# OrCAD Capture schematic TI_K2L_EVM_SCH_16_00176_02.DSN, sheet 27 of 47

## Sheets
27 PAGE16 : K2L_SOC-FPGA-AMC-2: size C; title: FPGA, FPGA 2pin conn, SPI Flash, LEDs
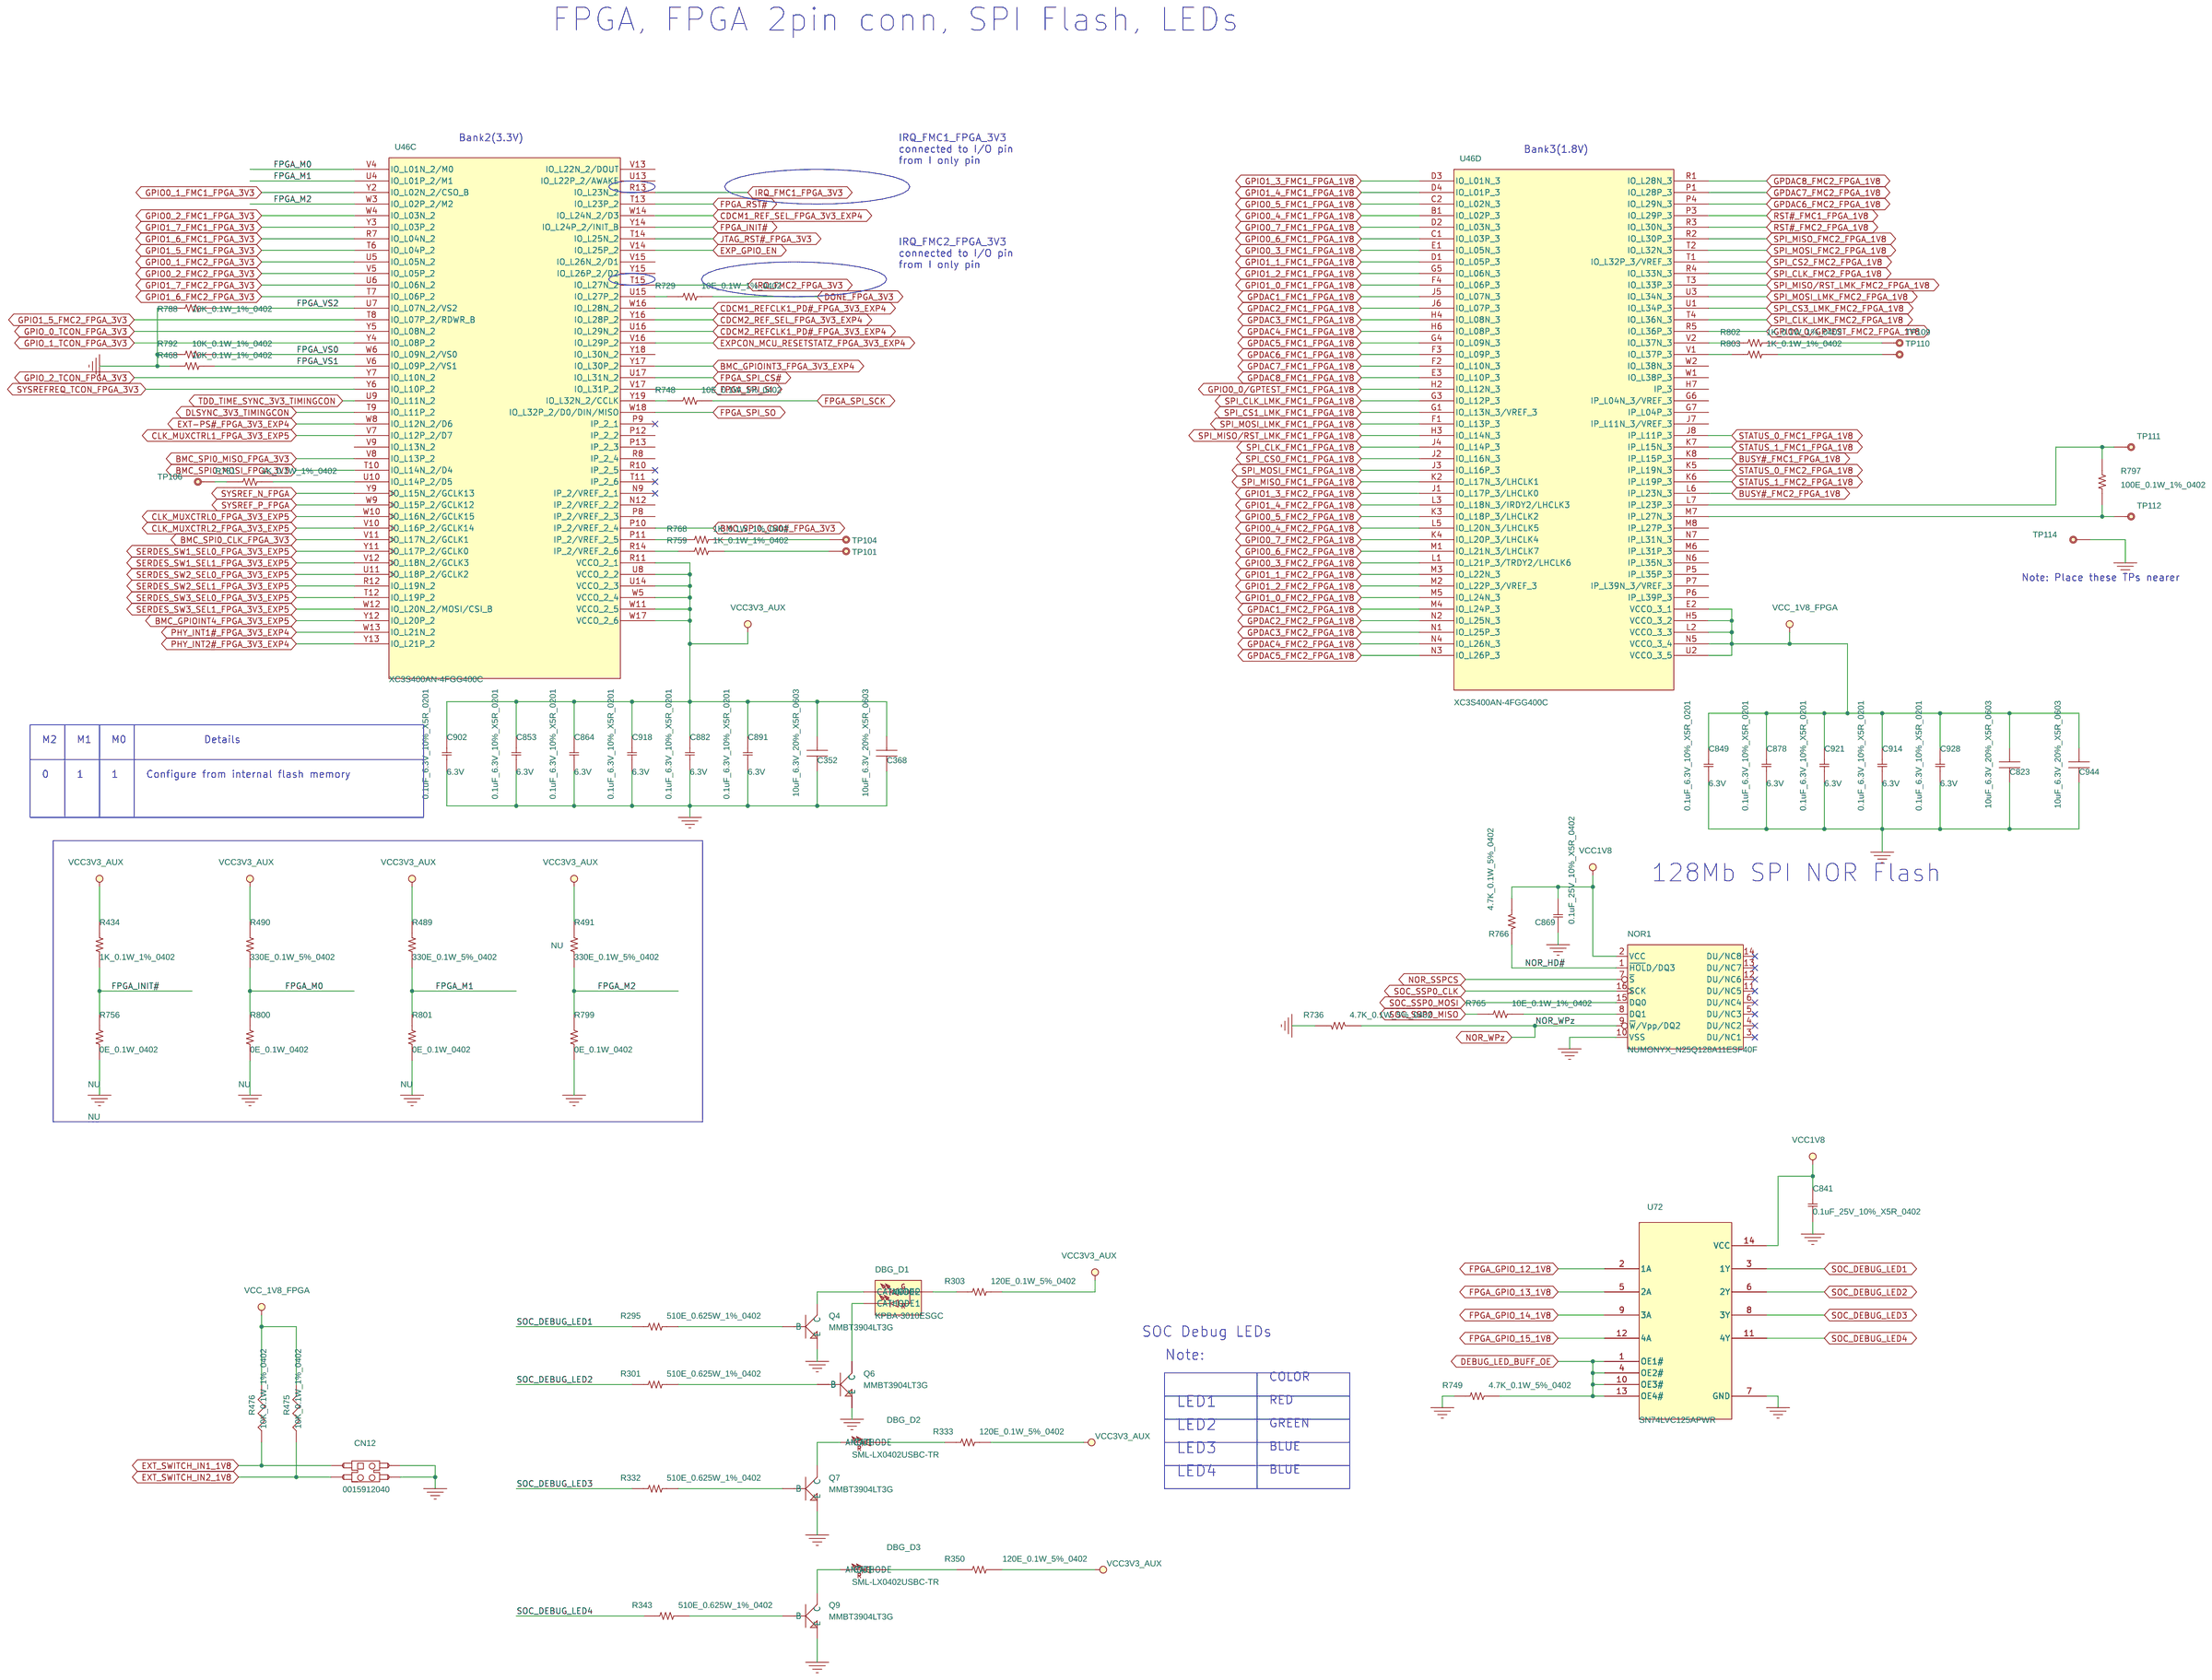
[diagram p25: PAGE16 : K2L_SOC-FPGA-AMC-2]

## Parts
sheet PAGE16 : K2L_SOC-FPGA-AMC-2
C352  10uF_6.3V_20%_X5R_0603  [C0603]
C368  10uF_6.3V_20%_X5R_0603  [C0603]
C823  10uF_6.3V_20%_X5R_0603  [C0603]
C841  0.1uF_25V_10%_X5R_0402  [C0402]
C849  0.1uF_6.3V_10%_X5R_0201  [CC0201_IPC7351_EINF]
C853  0.1uF_6.3V_10%_X5R_0201  [CC0201_IPC7351_EINF]
C864  0.1uF_6.3V_10%_X5R_0201  [CC0201_IPC7351_EINF]
C869  0.1uF_25V_10%_X5R_0402  [C0402]
C878  0.1uF_6.3V_10%_X5R_0201  [CC0201_IPC7351_EINF]
C882  0.1uF_6.3V_10%_X5R_0201  [CC0201_IPC7351_EINF]
C891  0.1uF_6.3V_10%_X5R_0201  [CC0201_IPC7351_EINF]
C902  0.1uF_6.3V_10%_X5R_0201  [CC0201_IPC7351_EINF]
C914  0.1uF_6.3V_10%_X5R_0201  [CC0201_IPC7351_EINF]
C918  0.1uF_6.3V_10%_X5R_0201  [CC0201_IPC7351_EINF]
C921  0.1uF_6.3V_10%_X5R_0201  [CC0201_IPC7351_EINF]
C928  0.1uF_6.3V_10%_X5R_0201  [CC0201_IPC7351_EINF]
C944  10uF_6.3V_20%_X5R_0603  [C0603]
CN12  15912040  [MOLEX_0015912040]
DBG_D1  KPBA-3010ESGC  [LED_KPBA-3010ESGC-F01]
DBG_D2  SML-LX0402USBC-TR  [LED_SML-LX0402]
DBG_D3  SML-LX0402USBC-TR  [LED_SML-LX0402]
NOR1  NUMONYX_N25Q128A11ESF40F  [SOIC_16P_50_406X406]
Q4  MMBT3904LT3G  [SOT-23]
Q6  MMBT3904LT3G  [SOT-23]
Q7  MMBT3904LT3G  [SOT-23]
Q9  MMBT3904LT3G  [SOT-23]
R295  510E_0.625W_1%_0402  [R0402]
R301  510E_0.625W_1%_0402  [R0402]
R303  120E_0.1W_5%_0402  [R0402]
R332  510E_0.625W_1%_0402  [R0402]
R333  120E_0.1W_5%_0402  [R0402]
R343  510E_0.625W_1%_0402  [R0402]
R350  120E_0.1W_5%_0402  [R0402]
R434  1K_0.1W_1%_0402  [R0402]
R468  10K_0.1W_1%_0402  [R0402]
R475  10K_0.1W_1%_0402  [R0402]
R476  10K_0.1W_1%_0402  [R0402]
R489  330E_0.1W_5%_0402  [R0402]
R490  330E_0.1W_5%_0402  [R0402]
R491  330E_0.1W_5%_0402  [R0402]
R729  10E_0.1W_1%_0402  [R0402]
R736  4.7K_0.1W_5%_0402  [R0402]
R748  10E_0.1W_1%_0402  [R0402]
R749  4.7K_0.1W_5%_0402  [R0402]
R756  0E_0.1W_0402  [R0402]
R759  1K_0.1W_1%_0402  [R0402]
R765  10E_0.1W_1%_0402  [R0402]
R766  4.7K_0.1W_5%_0402  [R0402]
R768  1K_0.1W_1%_0402  [R0402]
R781  1K_0.1W_1%_0402  [R0402]
R788  10K_0.1W_1%_0402  [R0402]
R792  10K_0.1W_1%_0402  [R0402]
R797  100E_0.1W_1%_0402  [R0402]
R799  0E_0.1W_0402  [R0402]
R800  0E_0.1W_0402  [R0402]
R801  0E_0.1W_0402  [R0402]
R802  1K_0.1W_1%_0402  [R0402]
R803  1K_0.1W_1%_0402  [R0402]
TP101  TP  [TP-S40]
TP104  TP  [TP-S40]
TP106  TP  [TP-S40]
TP109  TP  [TP-S40]
TP110  TP  [TP-S40]
TP111  TP  [TP-S40]
TP112  TP  [TP-S40]
TP114  TP  [TP-S40]
U72  SN74LVC125APWR  [SSOP65P640_14]
sheet PAGE17 : K2L_SOC-FPGA-AMC-3
U46  XC3S400AN-4FGG400C  [BGA400C100P20X20_2100X2100X243]  (sections A,B,C,D,E,F)

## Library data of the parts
C352 C368 C823 C944 = CAP: CAP CER 10UF 6.3V 20% X5R 0603; Distributor_name: DIGIKEY; Distributor_part_number: 587-3383-1-ND; EIC Part#: 03_00605_01; Manufacture: Taiyo Yuden; Manufacture Part Number: JMK107ABJ106MAHT; Manufacture(English): Taiyo Yuden; Manufacture_Part_Number: JMK107ABJ106MAHT; Manufacturer: Taiyo Yuden; Manufacturer_Part_No: JMK107ABJ106MAHT; Mfg: Taiyo Yuden; Mfg Part#: JMK107ABJ106MAHT; Mfr_name: Taiyo Yuden; Mfr_part_number: JMK107ABJ106MAHT; Price @ 1: 0.44000; Price @ 10K: 0.06105; Price @ 1K: 0.12650; Vendor: DIGIKEY; Vendor_Part_No: 587-3383-1-ND; eI Part#: 03_00605_01
C841 = 11_C_12: CAP CER 0.1UF 25V 10% X5R 0402; Distributor_name: DIGIKEY; Distributor_part_number: 445-4964-1-ND; EIC Part#: 03_00470_02; Manufacture: TDK Corporation; Manufacture Part Number: C1005X5R1E104K050BC; Manufacture(English): TDK Corporation; Manufacture_Part_Number: GRM155R61E104KA87D; Manufacturer: TDK Corporation; Manufacturer_Part_No: C1005X5R1E104K050BC; Mfg: Murata Electronics North America; Mfg Part#: 03_00470_02; Mfr_name: TDK Corporation; Mfr_part_number: C1005X5R1E104K050BC; Price @ 1: 0.10000; Price @ 1K: 0.00960; Vendor: DIGIKEY; Vendor Part#: 445-4964-1-ND; Vendor_Part_No: 445-4964-1-ND; eI Part#: 03_00470_02
C849 C853 C864 C878 C882 C891 C902 C914 C918 C921 C928 = 11_C_12: CAP CER 0.1UF 6.3V 10% X5R 0201; Alt Mfg: Taiyo Yuden; Alt Mfg Part#: TMK105BJ104KV-F; Characteristic: <Characteristic>; Distributor_name: DIGIKEY; Distributor_part_number: 445-1796-1-ND; EIC Part#: 03_00583_01; Manufacture: TDK Corporation; Manufacture Part Number: C0603X5R0J104K030BC; Manufacture(English): TDK Corporation; Manufacture_Part_Number: C0603X5R0J104K030BC; Manufacturer: TDK Corporation; Manufacturer_Part_No: C0603X5R0J104K030BC; Mfg: TDK Corporation; Mfg Part#: 03_00583_01; Mfr_name: TDK Corporation; Mfr_part_number: C0603X5R0J104K030BC; Oper. Temp. Range: -55°C ~ 85°C; Package: 0201; Price @ 1: 0.10000; Price @ 10K: 0.00675; Price @ 1K: 0.00810; ProcessType: SMT; RoHS: Yes; Tolerance: 10%; Vendor: DIGIKEY; Vendor Part#: 445-1796-2-ND; Vendor_Part_No: 445-1796-1-ND; Voltage: 6.3V; eI Part#: 03_00583_01
C869 = 11_C_0: CAP CER 0.1UF 25V 10% X5R 0402; Distributor_name: DIGIKEY; Distributor_part_number: 445-4964-1-ND; EIC Part#: 03_00470_02; Manufacture: TDK Corporation; Manufacture Part Number: C1005X5R1E104K050BC; Manufacture(English): TDK Corporation; Manufacture_Part_Number: GRM155R61E104KA87D; Manufacturer: TDK Corporation; Manufacturer_Part_No: C1005X5R1E104K050BC; Mfg: Murata Electronics North America; Mfg Part#: 03_00470_02; Mfr_name: TDK Corporation; Mfr_part_number: C1005X5R1E104K050BC; Price @ 1: 0.10000; Price @ 1K: 0.00960; Vendor: DIGIKEY; Vendor Part#: 445-4964-1-ND; Vendor_Part_No: 445-4964-1-ND; eI Part#: 03_00470_02
CN12 = XG8T-0441_0: CONN HEADER 4POS TIN SMD; Characteristic: 0015912040; Distributor_name: DIGIKEY; Distributor_part_number: WM9514-ND; EIC Part#: TBD; Manufacture: Molex Inc; Manufacture(English): Molex Inc; Manufacture_Part_Number: 0015912040; Manufacturer: Molex Inc; Mfg: Molex Inc; Mfg Part#: TBD; Mfr_name: Molex Inc; Price @ 1: 0.42000; Price @ 10K: 0.19770; Price @ 1K: 0.21247; Vendor: DIGIKEY; Vendor_Part_No: WM9514-ND; eI Part#: TBD
DBG_D1 = 130_LED_3P_KPBA-3010ESGC_0: LED Red/Green SMD 3.0x1.0mm 3P KPBA-3010ESGC; Distributor_name: Avnet Express; Distributor_part_number: KINKPBA3010ESGC; EIC Part#: TBD; Manufacture: Kingbright Corporation; Manufacture Part Number: KPBA-3010ESGC-F01; Manufacture(English): Kingbright Corporation; Manufacture_Part_Number: KPBA-3010ESGC-F01; Manufacturer: Kingbright Corporation; Manufacturer_Part_No: KPBA-3010ESGC-F01; Mfg: Kingbright Corporation; Mfg Part#: TBD; Mfr_name: Kingbright Corporation; Mfr_part_number: KPBA-3010ESGC-F01; Price @ 1: 0.68000; Price @ 10K: 0.34000; Price @ 1K: 0.34000; Vendor: Avnet Express; Vendor_Part_No: KINKPBA3010ESGC; eI Part#: TBD
DBG_D2 DBG_D3 = 130_LED_2P_B_KPA-1606QBC-D_2: Standard LEDs - SMD Blue Water Clear 470nm 20mcd; Distributor_name: Mouser; EIC Part#: TBD; Manufacture: Lumex Inc; Manufacture(English): Lumex Inc; Manufacturer: Lumex Inc; Mfg: Lumex Inc; Mfg Part#: TBD; Mfr_name: Lumex Inc; Vendor: Mouser; eI Part#: TBD
NOR1 = 141_NUMONYX_N25Q128A11BSF40F_0: IC N25Q128A11ESF40F FLASH SMD SO16 16P; Alt Mfg: Macronix International Co Ltd; Alt Mfg Part#: MX25U25635Fx_256Mb Part; Alternate_Mfr: Macronix International Co Ltd; Alternate_Partno: MX25U25635Fx_256Mb Part; Distributor_name: TBD; Distributor_part_number: TBD; EIC Part#: 01_01144_01; Manufacture: Micron; Manufacture Part Number: N25Q128A11ESF40F TR; Manufacture(English): Micron; Manufacture_Part_Number: N25Q128A11ESF40F TR; Manufacturer: Micron; Manufacturer_Part_No: N25Q128A11ESF40F TR; Mfg Part#: 01_01144_01; Mfr_name: Micron; Mfr_part_number: N25Q128A11ESF40F TR; Price @ 1K: 2.17623; Vendor: TBD; Vendor_Part_No: TBD; eI Part#: 01_01144_01
Q4 Q6 Q7 Q9 = 131_SOT-23A_BEC_0: TRANS NPN 2N3904 0.2A SMD TO-236AB; Distributor_name: DIGIKEY; Distributor_part_number: MMBT3904LT3GOSCT-ND; EIC Part#: 07_00016_04; Manufacture: ON Semiconductor; Manufacture(English): ON Semiconductor; Manufacturer: ON Semiconductor; Mfg Part#: 07_00016_04; Mfr_name: ON Semiconductor; Price @ 1: 0.11000; Price @ 10K: 0.01420; Price @ 1K: 0.02194; Vendor: DIGIKEY; Vendor_Part_No: MMBT3904LT3GOSCT-ND; eI Part#: 07_00016_04
R295 R301 R332 R343 = 10_R_0: RES 510 OHM 1/16W 1% 0402 SMD; Distributor_name: DIGIKEY; Distributor_part_number: 541-510LCT-ND; EIC Part#: 02_00958_01; Manufacture: Vishay Dale; Manufacture Part Number: CRCW0402510RFKED; Manufacture(English): Vishay Dale; Manufacture_Part_Number: CRCW0402510RFKED; Manufacturer: Vishay Dale; Manufacturer_Part_No: CRCW0402510RFKED; Mfg: Vishay Dale; Mfg Part#: CRCW0402510RFKED; Mfr_name: Vishay Dale; Mfr_part_number: CRCW0402510RFKED; Price @ 1: 0.10000; Price @ 10K: 0.00347; Price @ 1K: 0.00672; Vendor: DigiKey; Vendor_Part_No: 541-510LCT-ND; eI Part#: 02_00958_01
R303 R333 R350 = 10_R_0: RES 120 OHM 1/10W 5% 0402 SMD; Distributor_name: DIGIKEY; Distributor_part_number: P120JCT-ND; EIC Part#: TBD; Manufacture: Panasonic - ECG; Manufacture Part Number: ERJ-2GEJ121X; Manufacture(English): Panasonic - ECG; Manufacture_Part_Number: ERJ-2GEJ121X; Manufacturer: Panasonic - ECG; Manufacturer_Part_No: ERJ-2GEJ121X; Mfg Part#: TBD; Mfr_name: Panasonic - ECG; Mfr_part_number: ERJ-2GEJ121X; Price @ 1: 0.10000; Price @ 10K: 0.00248; Price @ 1K: 0.00480; Vendor: DIGIKEY; Vendor_Part_No: P120JCT-ND; eI Part#: 02_00348_01
R434 R759 R768 R781 R802 R803 = 10_R_0: RES 1.00K OHM 1/10W 1% 0402 SMD; Distributor_name: DIGIKEY; Distributor_part_number: P1.00KLCT-ND; EIC Part#: 02_00045_01; Manufacture: Panasonic - ECG; Manufacture Part Number: ERJ-2RKF1001X; Manufacture(English): Panasonic - ECG; Manufacture_Part_Number: ERJ-2RKF1001X; Manufacturer: Panasonic - ECG; Manufacturer_Part_No: ERJ-2RKF1001X; Mfg Part#: 02_00045_01; Mfr_name: Panasonic - ECG; Mfr_part_number: ERJ-2RKF1001X; Price @ 1: 0.10000; Price @ 10K: 0.00347; Price @ 1K: 0.00672; Vendor: DIGIKEY; Vendor_Part_No: P1.00KLCT-ND; eI Part#: 02_00045_01
R468 R788 R792 = 10_R_0: RES 10K OHM 1/10W 1% 0402 SMD; Distributor_name: DIGIKEY; Distributor_part_number: P10.0KLCT-ND; EIC Part#: 02_00027_01; Manufacture: Panasonic - ECG; Manufacture Part Number: ERJ-2RKF1002X; Manufacture(English): Panasonic - ECG; Manufacture_Part_Number: ERJ-2RKF1002X; Manufacturer: Panasonic - ECG; Manufacturer_Part_No: ERJ-2RKF1002X; Mfg Part#: 02_00027_01; Mfr_name: Panasonic - ECG; Mfr_part_number: ERJ-2RKF1002X; Package: 0402; Price @ 1: 0.10000; Price @ 10K: 0.00347; Price @ 1K: 0.00672; Vendor: DIGIKEY; Vendor_Part_No: P10.0KLCT-ND; eI Part#: 02_00027_01
R475 R476 = DISC_RESISTOR: RES 10K OHM 1/10W 1% 0402 SMD; Distributor_name: DIGIKEY; Distributor_part_number: P10.0KLCT-ND; EIC Part#: 02_00027_01; Manufacture: Panasonic - ECG; Manufacture Part Number: ERJ-2RKF1002X; Manufacture(English): Panasonic - ECG; Manufacture_Part_Number: ERJ-2RKF1002X; Manufacturer: Panasonic - ECG; Manufacturer_Part_No: ERJ-2RKF1002X; Mfg Part#: 02_00027_01; Mfr_name: Panasonic - ECG; Mfr_part_number: ERJ-2RKF1002X; Package: 0402; Price @ 1: 0.10000; Price @ 10K: 0.00347; Price @ 1K: 0.00672; Vendor: DIGIKEY; Vendor_Part_No: P10.0KLCT-ND; eI Part#: 02_00027_01
R489 = 10_R_0: RES 330 OHM 1/10W 5% 0402 SMD; Distributor_name: DIGIKEY; Distributor_part_number: P330JCT-ND; EIC Part#: 02_00032_01; Manufacture: Panasonic - ECG; Manufacture Part Number: ERJ-2GEJ331X; Manufacture(English): Panasonic - ECG; Manufacture_Part_Number: ERJ-2GEJ331X; Manufacturer: Panasonic - ECG; Manufacturer_Part_No: ERJ-2GEJ331X; Mfg Part#: 02_00032_01; Mfr_name: Panasonic - ECG; Mfr_part_number: ERJ-2GEJ331X; Price @ 1: 0.10000; Price @ 10K: 0.00248; Price @ 1K: 0.00480; Vendor: DIGIKEY; Vendor_Part_No: P330JCT-ND; eI Part#: 02_00045_01
R490 = 10_R_0: RES 330 OHM 1/10W 5% 0402 SMD; Distributor_name: DIGIKEY; Distributor_part_number: P330JCT-ND; EIC Part#: 02_00032_01; Manufacture: Panasonic - ECG; Manufacture Part Number: ERJ-2GEJ331X; Manufacture(English): Panasonic - ECG; Manufacture_Part_Number: ERJ-2GEJ331X; Manufacturer: Panasonic - ECG; Manufacturer_Part_No: ERJ-2GEJ331X; Mfg Part#: 02_00032_01; Mfr_name: Panasonic - ECG; Mfr_part_number: ERJ-2GEJ331X; Price @ 1: 0.10000; Price @ 10K: 0.00248; Price @ 1K: 0.00480; Vendor: DIGIKEY; Vendor_Part_No: P330JCT-ND; eI Part#: 02_00027_01
R491 = 10_R_0: RES 330 OHM 1/10W 5% 0402 SMD; Distributor_name: DIGIKEY; Distributor_part_number: P330JCT-ND; EIC Part#: 02_00032_01; Manufacture: Panasonic - ECG; Manufacture Part Number: ERJ-2GEJ331X; Manufacture(English): Panasonic - ECG; Manufacture_Part_Number: ERJ-2GEJ331X; Manufacturer: Panasonic - ECG; Manufacturer_Part_No: ERJ-2GEJ331X; Mfg Part#: 02_00032_01; Mfr_name: Panasonic - ECG; Mfr_part_number: ERJ-2GEJ331X; Mounting Status: NU; Mounting_Status: NU; Price @ 1: 0.10000; Price @ 10K: 0.00248; Price @ 1K: 0.00480; Vendor: DIGIKEY; Vendor_Part_No: P330JCT-ND; eI Part#: 02_00045_01
R729 = 10_R_0: RES 10.0 OHM 1/10W 1% 0402 SMD; Distributor_name: DIGIKEY; Distributor_part_number: P10.0LCT-ND; EIC Part#: 02_00348_01; Manufacture: Panasonic - ECG; Manufacture Part Number: ERJ-2RKF10R0X; Manufacture(English): Panasonic - ECG; Manufacture_Part_Number: ERJ-2RKF10R0X; Manufacturer: Panasonic - ECG; Manufacturer_Part_No: ERJ-2RKF10R0X; Mfg: Panasonic Electronic Components; Mfg Part#: 02_00348_01; Mfr_name: Panasonic - ECG; Mfr_part_number: ERJ-2RKF10R0X; Price @ 1: 0.10000; Price @ 10K: 0.00347; Price @ 1K: 0.00672; Vendor: DIGIKEY; Vendor_Part_No: P10.0LCT-ND; eI Part#: 02_00019_01
R736 R749 R766 = 10_R_0: RES 4.7K OHM 1/10W 5% 0402 SMD; Distributor_name: DIGIKEY; Distributor_part_number: P4.7KJCT-ND; EIC Part#: 02_00023_01; Manufacture: Panasonic - ECG; Manufacture Part Number: ERJ-2GEJ472X; Manufacture(English): Panasonic - ECG; Manufacture_Part_Number: ERJ-2GEJ472X; Manufacturer: Panasonic - ECG; Manufacturer_Part_No: ERJ-2GEJ472X; Mfg: Panasonic Electronic Components; Mfg Part#: 02_00266_01; Mfr_name: Panasonic - ECG; Mfr_part_number: ERJ-2GEJ472X; Price @ 1: 0.10000; Price @ 10K: 0.00347; Price @ 1K: 0.00672; Vendor: DIGIKEY; Vendor_Part_No: P4.7KJCT-ND; eI Part#: 02_00023_01
R748 = 10_R_0: RES 10.0 OHM 1/10W 1% 0402 SMD; Distributor_name: DIGIKEY; Distributor_part_number: P10.0LCT-ND; EIC Part#: 02_00348_01; Manufacture: Panasonic - ECG; Manufacture Part Number: ERJ-2RKF10R0X; Manufacture(English): Panasonic - ECG; Manufacture_Part_Number: ERJ-2RKF10R0X; Manufacturer: Panasonic - ECG; Manufacturer_Part_No: ERJ-2RKF10R0X; Mfg: Panasonic Electronic Components; Mfg Part#: 02_00348_01; Mfr_name: Panasonic - ECG; Mfr_part_number: ERJ-2RKF10R0X; Price @ 1: 0.10000; Price @ 10K: 0.00347; Price @ 1K: 0.00672; Vendor: DIGIKEY; Vendor_Part_No: P10.0LCT-ND; eI Part#: 02_00027_01
R756 R800 R801 = 10_R_0: RES 0.0 OHM 1/10W JUMP 0402 SMD; Distributor_name: DIGIKEY; Distributor_part_number: P0.0JCT-ND; EIC Part#: 02_00019_01; Manufacture: Panasonic - ECG; Manufacture Part Number: ERJ-2GE0R00X; Manufacture(English): Panasonic - ECG; Manufacture_Part_Number: ERJ-2GE0R00X; Manufacturer: Panasonic - ECG; Manufacturer_Part_No: ERJ-2GE0R00X; Mfg: PANASONIC ELECTRONIC COMPONENTS (VA); Mfg Part#: 02_00019_01; Mfr_name: Panasonic - ECG; Mfr_part_number: ERJ-2GE0R00X; Mounting Status: NU; Mounting_Status: NU; Price @ 1: 0.05000; Price @ 10K: 0.00248; Price @ 1K: 0.00480; Vendor: DIGIKEY; Vendor_Part_No: P0.0JCT-ND; eI Part#: 02_00019_01
R765 = 10_R_0: RES 10.0 OHM 1/10W 1% 0402 SMD; Distributor_name: DIGIKEY; Distributor_part_number: P10.0LCT-ND; EIC Part#: 02_00348_01; Manufacture: Panasonic - ECG; Manufacture Part Number: ERJ-2RKF10R0X; Manufacture(English): Panasonic - ECG; Manufacture_Part_Number: ERJ-2RKF10R0X; Manufacturer: Panasonic - ECG; Manufacturer_Part_No: ERJ-2RKF10R0X; Mfg: Panasonic Electronic Components; Mfg Part#: 02_00348_01; Mfr_name: Panasonic - ECG; Mfr_part_number: ERJ-2RKF10R0X; Price @ 1: 0.10000; Price @ 10K: 0.00347; Price @ 1K: 0.00672; Vendor: DIGIKEY; Vendor_Part_No: P10.0LCT-ND; eI Part#: 02_00266_01
R797 = 10_R_0: RES 100 OHM 1/10W 1% 0402 SMD; Distributor_name: DIGIKEY; Distributor_part_number: P100LCT-ND; EIC Part#: 02_00043_02; Manufacture: Panasonic - ECG; Manufacture Part Number: ERJ-2RKF1000X; Manufacture(English): Panasonic - ECG; Manufacture_Part_Number: ERJ-2RKF1000X; Manufacturer: Panasonic - ECG; Manufacturer_Part_No: ERJ-2RKF1000X; Mfg Part#: 02_00043_02; Mfr_name: Panasonic - ECG; Mfr_part_number: ERJ-2RKF1000X; Price @ 1: 0.10000; Price @ 10K: 0.00347; Price @ 1K: 0.00672; Vendor: DIGIKEY; Vendor_Part_No: P100LCT-ND; eI Part#: 02_00334_02
R799 = 10_R_0: RES 0.0 OHM 1/10W JUMP 0402 SMD; Distributor_name: DIGIKEY; Distributor_part_number: P0.0JCT-ND; EIC Part#: 02_00019_01; Manufacture: Panasonic - ECG; Manufacture Part Number: ERJ-2GE0R00X; Manufacture(English): Panasonic - ECG; Manufacture_Part_Number: ERJ-2GE0R00X; Manufacturer: Panasonic - ECG; Manufacturer_Part_No: ERJ-2GE0R00X; Mfg: PANASONIC ELECTRONIC COMPONENTS (VA); Mfg Part#: 02_00019_01; Mfr_name: Panasonic - ECG; Mfr_part_number: ERJ-2GE0R00X; Price @ 1: 0.05000; Price @ 10K: 0.00248; Price @ 1K: 0.00480; Vendor: DIGIKEY; Vendor_Part_No: P0.0JCT-ND; eI Part#: 02_00019_01
TP101 TP104 TP106 TP109-TP112 TP114 = 00_TP28_0: TEST PAD TP; Distributor_name: NA; Distributor_part_number: NA; EIC Part#: NA; Manufacture: NA; Manufacture Part Number: NA; Manufacture(English): NA; Manufacture_Part_Number: NA; Manufacturer: NA; Manufacturer_Part_No: NA; Mfg: NA; Mfg Part#: NA; Mfr_name: NA; Mfr_part_number: NA; Price @ 1: NA; Price @ 10K: NA; Price @ 1K: NA; Vendor: NA; Vendor_Part_No: NA; eI Part#: TBD
U72 = SN74LVC125A_1: IC BUS BUFF TRI-ST QD 14TSSOP; Distributor_name: DIGIKEY; Distributor_part_number: 296-1222-1-ND; EIC Part#: 01_00923_01; Manufacture: TI; Manufacture(English): TI; Manufacturer: TI; Mfg Part#: 01_00923_01; Mfr_name: TI; Price @ 1: 0.47000; Price @ 10K: 0.11550; Price @ 1K: 0.12950; Vendor: DIGIKEY; Vendor_Part_No: 296-1222-1-ND; eI Part#: 08_00006_01
U46 = XC3S400AN-4FGG400C: IC SPARTAN-3AN FPGA 400K 400FBGA; Color: Default; Distributor_name: DIGIKEY; Distributor_part_number: 122-1554-ND; EIC Part#: 01_01149_01; Location X-Coordinate: 0; Location Y-Coordinate: 0; Manufacture: Xilinx Inc; Manufacture(English): Xilinx Inc; Manufacturer: Xilinx Inc; Mfg: Xilinx Inc; Mfg Part#: 01_01149_01; Mfr_name: Xilinx Inc; Price @ 1: 27.86000; Primitive: DEFAULT; SPLIT_INST: TRUE; SWAP_INFO: (S1+S2+S3+S4+S5+S6); Vendor: DIGIKEY; Vendor_Part_No: 122-1554-ND; eI Part#: 01_01138_01

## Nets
GND: C352.2 C368.2 C823.2 C841.2 C849.2 C853.2 C864.2 C869.1 C878.2 C882.2 C891.2 C902.2 C914.2 C918.2 C921.2 C928.2 C944.2 CN12.B1 CN12.B2 NOR1.10(VSS) Q4.2(E) Q6.2(E) Q7.2(E) Q9.2(E) R468.1 R736.1 R749.1 R756.2 R788.1 R792.1 R799.2 R800.2 R801.2 TP114.1 U72.7(GND) ; also on sheet 1 2 3 4 5 6 8 10 11 12 13 14 15 16 17 18 19 20 21 22 24 25 26 28 29 33 34 35 36 37 40 41 42 43 45 46 47
VCC1V8: C841.1 C869.2 NOR1.2(VCC) R766.2 U72.14(VCC) ; also on sheet 2 6 8 11 19 21 22 25 26 29 33 34 36 37 41
VCC3V3_AUX: C352.1 C368.1 C853.1 C864.1 C882.1 C891.1 C902.1 C918.1 R303.2 R333.2 R350.2 R434.1 R489.1 R490.1 R491.1 U46.R11(VCCO_2_1) U46.U8(VCCO_2_2) U46.U14(VCCO_2_3) U46.W5(VCCO_2_4) U46.W11(VCCO_2_5) U46.W17(VCCO_2_6) ; also on sheet 2 4 6 8 11 12 13 16 18 19 22 25 26 28 29 33 35 37 40 45 47
VCC_1V8_FPGA: C823.1 C849.1 C878.1 C914.1 C921.1 C928.1 C944.1 R475.2 R476.2 U46.E2(VCCO_3_1) U46.H5(VCCO_3_2) U46.L2(VCCO_3_3) U46.N5(VCCO_3_4) U46.U2(VCCO_3_5) ; also on sheet 28 29 35
BMC_GPIOINT3_FPGA_3V3_EXP4: U46.Y17(IO_L30P_2) ; also on sheet 5
BMC_GPIOINT4_FPGA_3V3_EXP5: U46.Y12(IO_L20P_2) ; also on sheet 5
BMC_SPI0_CLK_FPGA_3V3: U46.V11(IO_L17N_2/GCLK1) ; also on sheet 5 11 13
BMC_SPI0_CS0#_FPGA_3V3: U46.P10(IP_2/VREF_2_4) ; also on sheet 5
BMC_SPI0_MISO_FPGA_3V3: U46.V8(IO_L13P_2) ; also on sheet 5 11 13
BMC_SPI0_MOSI_FPGA_3V3: U46.T10(IO_L14N_2/D4) ; also on sheet 5 11 13
BUSY#_FMC1_FPGA_1V8: U46.K8(IP_L15P_3) ; also on sheet 43
BUSY#_FMC2_FPGA_1V8: U46.L6(IP_L23N_3) ; also on sheet 46
CDCM1_REF_SEL_FPGA_3V3_EXP4: U46.W14(IO_L24N_2/D3) ; also on sheet 11
CDCM1_REFCLK1_PD#_FPGA_3V3_EXP4: U46.W16(IO_L28N_2) ; also on sheet 11
CDCM2_REF_SEL_FPGA_3V3_EXP4: U46.Y16(IO_L28P_2) ; also on sheet 13
CDCM2_REFCLK1_PD#_FPGA_3V3_EXP4: U46.U16(IO_L29N_2) ; also on sheet 13
CLK_MUXCTRL0_FPGA_3V3_EXP5: U46.W10(IO_L16N_2/GCLK15) ; also on sheet 16
CLK_MUXCTRL1_FPGA_3V3_EXP5: U46.V7(IO_L12P_2/D7) ; also on sheet 16
CLK_MUXCTRL2_FPGA_3V3_EXP5: U46.V10(IO_L16P_2/GCLK14) ; also on sheet 16
DEBUG_LED_BUFF_OE: R749.2 U72.1(OE1#) U72.4(OE2#) U72.10(OE3#) U72.13(OE4#) ; also on sheet 5
DLSYNC_3V3_TIMINGCON: U46.T9(IO_L11P_2) ; also on sheet 29
DONE_FPGA_3V3: R729.2 ; also on sheet 29
EXP_GPIO_EN: U46.V14(IO_L25P_2) ; also on sheet 21
EXPCON_MCU_RESETSTATZ_FPGA_3V3_EXP4: U46.V16(IO_L29P_2) ; also on sheet 26
EXT-PS#_FPGA_3V3_EXP4: U46.W8(IO_L12N_2/D6) ; also on sheet 26
EXT_SWITCH_IN1_1V8: CN12.A1 R476.1 ; also on sheet 28
EXT_SWITCH_IN2_1V8: CN12.A2 R475.1 ; also on sheet 28
FPGA_GPIO_12_1V8: U72.2(1A) ; also on sheet 28
FPGA_GPIO_13_1V8: U72.5(2A) ; also on sheet 28
FPGA_GPIO_14_1V8: U72.9(3A) ; also on sheet 28
FPGA_GPIO_15_1V8: U72.12(4A) ; also on sheet 28
FPGA_INIT#: R434.2 R756.1 U46.Y14(IO_L24P_2/INIT_B)
FPGA_M0: R490.2 R800.1 U46.V4(IO_L01N_2/M0)
FPGA_M1: R489.2 R801.1 U46.U4(IO_L01P_2/M1)
FPGA_M2: R491.2 R799.1 U46.W3(IO_L02P_2/M2)
FPGA_RST#: U46.T13(IO_L23P_2) ; also on sheet 5
FPGA_SPI_CS#: U46.U17(IO_L31N_2) ; also on sheet 29
FPGA_SPI_SCK: R748.2 ; also on sheet 29
FPGA_SPI_SI: U46.V17(IO_L31P_2) ; also on sheet 29
FPGA_SPI_SO: U46.W18(IO_L32P_2/D0/DIN/MISO) ; also on sheet 29
FPGA_VS0: R792.2 U46.W6(IO_L09N_2/VS0)
FPGA_VS1: R468.2 U46.V6(IO_L09P_2/VS1)
FPGA_VS2: R788.2 U46.U7(IO_L07N_2/VS2)
GPDAC1_FMC1_FPGA_1V8: U46.J5(IO_L07N_3) ; also on sheet 43
GPDAC1_FMC2_FPGA_1V8: U46.M4(IO_L24P_3) ; also on sheet 46
GPDAC2_FMC1_FPGA_1V8: U46.J6(IO_L07P_3) ; also on sheet 43
GPDAC2_FMC2_FPGA_1V8: U46.N2(IO_L25N_3) ; also on sheet 46
GPDAC3_FMC1_FPGA_1V8: U46.H4(IO_L08N_3) ; also on sheet 43
GPDAC3_FMC2_FPGA_1V8: U46.N1(IO_L25P_3) ; also on sheet 46
GPDAC4_FMC1_FPGA_1V8: U46.H6(IO_L08P_3) ; also on sheet 43
GPDAC4_FMC2_FPGA_1V8: U46.N4(IO_L26N_3) ; also on sheet 46
GPDAC5_FMC1_FPGA_1V8: U46.G4(IO_L09N_3) ; also on sheet 43
GPDAC5_FMC2_FPGA_1V8: U46.N3(IO_L26P_3) ; also on sheet 46
GPDAC6_FMC1_FPGA_1V8: U46.F3(IO_L09P_3) ; also on sheet 43
GPDAC6_FMC2_FPGA_1V8: U46.P4(IO_L29N_3) ; also on sheet 46
GPDAC7_FMC1_FPGA_1V8: U46.F2(IO_L10N_3) ; also on sheet 43
GPDAC7_FMC2_FPGA_1V8: U46.P1(IO_L28P_3) ; also on sheet 46
GPDAC8_FMC1_FPGA_1V8: U46.E3(IO_L10P_3) ; also on sheet 43
GPDAC8_FMC2_FPGA_1V8: U46.R1(IO_L28N_3) ; also on sheet 46
GPIO0_0/GPTEST_FMC1_FPGA_1V8: U46.H2(IO_L12N_3) ; also on sheet 43
GPIO0_0/GPTEST_FMC2_FPGA_1V8: U46.R5(IO_L36P_3) ; also on sheet 46
GPIO0_1_FMC1_FPGA_3V3: U46.Y2(IO_L02N_2/CSO_B) ; also on sheet 43
GPIO0_1_FMC2_FPGA_3V3: U46.U5(IO_L05N_2) ; also on sheet 46
GPIO0_2_FMC1_FPGA_3V3: U46.W4(IO_L03N_2) ; also on sheet 43
GPIO0_2_FMC2_FPGA_3V3: U46.V5(IO_L05P_2) ; also on sheet 46
GPIO0_3_FMC1_FPGA_1V8: U46.E1(IO_L05N_3) ; also on sheet 43
GPIO0_3_FMC2_FPGA_1V8: U46.L1(IO_L21P_3/TRDY2/LHCLK6) ; also on sheet 46
GPIO0_4_FMC1_FPGA_1V8: U46.B1(IO_L02P_3) ; also on sheet 43
GPIO0_4_FMC2_FPGA_1V8: U46.L5(IO_L20N_3/LHCLK5) ; also on sheet 46
GPIO0_5_FMC1_FPGA_1V8: U46.C2(IO_L02N_3) ; also on sheet 43
GPIO0_5_FMC2_FPGA_1V8: U46.K3(IO_L18P_3/LHCLK2) ; also on sheet 46
GPIO0_6_FMC1_FPGA_1V8: U46.C1(IO_L03P_3) ; also on sheet 43
GPIO0_6_FMC2_FPGA_1V8: U46.M1(IO_L21N_3/LHCLK7) ; also on sheet 46
GPIO0_7_FMC1_FPGA_1V8: U46.D2(IO_L03N_3) ; also on sheet 43
GPIO0_7_FMC2_FPGA_1V8: U46.K4(IO_L20P_3/LHCLK4) ; also on sheet 46
GPIO1_0_FMC1_FPGA_1V8: U46.F4(IO_L06P_3) ; also on sheet 43
GPIO1_0_FMC2_FPGA_1V8: U46.M5(IO_L24N_3) ; also on sheet 46
GPIO1_1_FMC1_FPGA_1V8: U46.D1(IO_L05P_3) ; also on sheet 43
GPIO1_1_FMC2_FPGA_1V8: U46.M3(IO_L22N_3) ; also on sheet 46
GPIO1_2_FMC1_FPGA_1V8: U46.G5(IO_L06N_3) ; also on sheet 43
GPIO1_2_FMC2_FPGA_1V8: U46.M2(IO_L22P_3/VREF_3) ; also on sheet 46
GPIO1_3_FMC1_FPGA_1V8: U46.D3(IO_L01N_3) ; also on sheet 43
GPIO1_3_FMC2_FPGA_1V8: U46.J1(IO_L17P_3/LHCLK0) ; also on sheet 46
GPIO1_4_FMC1_FPGA_1V8: U46.D4(IO_L01P_3) ; also on sheet 43
GPIO1_4_FMC2_FPGA_1V8: U46.L3(IO_L18N_3/IRDY2/LHCLK3) ; also on sheet 46
GPIO1_5_FMC1_FPGA_3V3: U46.T6(IO_L04P_2) ; also on sheet 43
GPIO1_5_FMC2_FPGA_3V3: U46.T8(IO_L07P_2/RDWR_B) ; also on sheet 46
GPIO1_6_FMC1_FPGA_3V3: U46.R7(IO_L04N_2) ; also on sheet 43
GPIO1_6_FMC2_FPGA_3V3: U46.T7(IO_L06P_2) ; also on sheet 46
GPIO1_7_FMC1_FPGA_3V3: U46.Y3(IO_L03P_2) ; also on sheet 43
GPIO1_7_FMC2_FPGA_3V3: U46.U6(IO_L06N_2) ; also on sheet 46
GPIO_0_TCON_FPGA_3V3: U46.Y5(IO_L08N_2) ; also on sheet 29
GPIO_1_TCON_FPGA_3V3: U46.Y4(IO_L08P_2) ; also on sheet 29
GPIO_2_TCON_FPGA_3V3: U46.Y7(IO_L10N_2) ; also on sheet 29
IRQ_FMC1_FPGA_3V3: U46.R13(IO_L23N_2) ; also on sheet 43
IRQ_FMC2_FPGA_3V3: U46.T15(IO_L27N_2) ; also on sheet 46
JTAG_RST#_FPGA_3V3: U46.T14(IO_L25N_2) ; also on sheet 29
NOR_HD#: NOR1.1(~{HOL}D/DQ3) R766.1
NOR_SSPCS: NOR1.7(~{S}) ; also on sheet 29
NOR_WPz: NOR1.9(~{W}/Vpp/DQ2) R736.2 ; also on sheet 28
PHY_INT1#_FPGA_3V3_EXP4: U46.W13(IO_L21N_2) ; also on sheet 2
PHY_INT2#_FPGA_3V3_EXP4: U46.Y13(IO_L21P_2) ; also on sheet 2
RST#_FMC1_FPGA_1V8: U46.P3(IO_L29P_3) ; also on sheet 43
RST#_FMC2_FPGA_1V8: U46.R3(IO_L30N_3) ; also on sheet 46
SERDES_SW1_SEL0_FPGA_3V3_EXP5: U46.Y11(IO_L17P_2/GCLK0) ; also on sheet 45
SERDES_SW1_SEL1_FPGA_3V3_EXP5: U46.V12(IO_L18N_2/GCLK3) ; also on sheet 45
SERDES_SW2_SEL0_FPGA_3V3_EXP5: U46.U11(IO_L18P_2/GCLK2) ; also on sheet 47
SERDES_SW2_SEL1_FPGA_3V3_EXP5: U46.R12(IO_L19N_2) ; also on sheet 47
SERDES_SW3_SEL0_FPGA_3V3_EXP5: U46.T12(IO_L19P_2) ; also on sheet 40
SERDES_SW3_SEL1_FPGA_3V3_EXP5: U46.W12(IO_L20N_2/MOSI/CSI_B) ; also on sheet 40
SOC_DEBUG_LED1: R295.1 U72.3(1Y)
SOC_DEBUG_LED2: R301.1 U72.6(2Y)
SOC_DEBUG_LED3: R332.1 U72.8(3Y)
SOC_DEBUG_LED4: R343.1 U72.11(4Y)
SOC_SSP0_CLK: NOR1.16(SCK) ; also on sheet 29
SOC_SSP0_MISO: R765.1 ; also on sheet 29
SOC_SSP0_MOSI: NOR1.15(DQ0) ; also on sheet 29
SPI_CLK_FMC1_FPGA_1V8: U46.J4(IO_L14P_3) ; also on sheet 43
SPI_CLK_FMC2_FPGA_1V8: U46.R4(IO_L33N_3) ; also on sheet 46
SPI_CLK_LMK_FMC1_FPGA_1V8: U46.G3(IO_L12P_3) ; also on sheet 43
SPI_CLK_LMK_FMC2_FPGA_1V8: U46.T4(IO_L36N_3) ; also on sheet 46
SPI_CS0_FMC1_FPGA_1V8: U46.J2(IO_L16N_3) ; also on sheet 43
SPI_CS1_LMK_FMC1_FPGA_1V8: U46.G1(IO_L13N_3/VREF_3) ; also on sheet 43
SPI_CS2_FMC2_FPGA_1V8: U46.T1(IO_L32P_3/VREF_3) ; also on sheet 46
SPI_CS3_LMK_FMC2_FPGA_1V8: U46.U1(IO_L34P_3) ; also on sheet 46
SPI_MISO/RST_LMK_FMC1_FPGA_1V8: U46.H3(IO_L14N_3) ; also on sheet 43
SPI_MISO/RST_LMK_FMC2_FPGA_1V8: U46.T3(IO_L33P_3) ; also on sheet 46
SPI_MISO_FMC1_FPGA_1V8: U46.K2(IO_L17N_3/LHCLK1) ; also on sheet 43
SPI_MISO_FMC2_FPGA_1V8: U46.R2(IO_L30P_3) ; also on sheet 46
SPI_MOSI_FMC1_FPGA_1V8: U46.J3(IO_L16P_3) ; also on sheet 43
SPI_MOSI_FMC2_FPGA_1V8: U46.T2(IO_L32N_3) ; also on sheet 46
SPI_MOSI_LMK_FMC1_FPGA_1V8: U46.F1(IO_L13P_3) ; also on sheet 43
SPI_MOSI_LMK_FMC2_FPGA_1V8: U46.U3(IO_L34N_3) ; also on sheet 46
STATUS_0_FMC1_FPGA_1V8: U46.J8(IP_L11P_3) ; also on sheet 43
STATUS_0_FMC2_FPGA_1V8: U46.K5(IP_L19N_3) ; also on sheet 46
STATUS_1_FMC1_FPGA_1V8: U46.K7(IP_L15N_3) ; also on sheet 43
STATUS_1_FMC2_FPGA_1V8: U46.K6(IP_L19P_3) ; also on sheet 46
SYSREF_N_FPGA: U46.Y9(IO_L15N_2/GCLK13) ; also on sheet 28
SYSREF_P_FPGA: U46.W9(IO_L15P_2/GCLK12) ; also on sheet 28
SYSREFREQ_TCON_FPGA_3V3: U46.Y6(IO_L10P_2) ; also on sheet 29
TDD_TIME_SYNC_3V3_TIMINGCON: U46.U9(IO_L11N_2) ; also on sheet 29
N17639760: DBG_D3.2(ANODE) R350.1
N17639810: Q7.1(B) R332.2
N17639831: Q9.1(B) R343.2
N17639877: DBG_D2.2(ANODE) R333.1
N17639909: Q4.1(B) R295.2
N17639911: DBG_D1.2(CATHODE1) Q6.3(C)
N17639931: Q6.1(B) R301.2
N17639959: DBG_D1.3(CATHODE2) Q4.3(C)
N17639963: DBG_D2.1(CATHODE) Q7.3(C)
N17639967: DBG_D1.1(ANODE) R303.1
N17639971: DBG_D3.1(CATHODE) Q9.3(C)
N17750733: NOR1.8(DQ1) R765.2
N18912236: R768.2 U46.P11(IP_2/VREF_2_5)
N18912438: R759.2 U46.R14(IP_2/VREF_2_6)
N18912600: R781.1 U46.U10(IO_L14P_2/D5)
N18912628: R781.2 TP106.1
N18912862: R802.2 U46.V2(IO_L37N_3)
N18912865: R803.2 U46.V1(IO_L37P_3)
N18912868: R802.1 TP109.1
N18912871: R803.1 TP110.1
N18913448: R797.2 TP112.1 U46.M7(IP_L27N_3)
N18913450: R797.1 TP111.1 U46.L7(IP_L23P_3)
N18914575: R768.1 TP104.1
N18914593: R759.1 TP101.1
N19725041: R748.1 U46.Y19(IO_L32N_2/CCLK)
N21616465: R729.1 U46.U15(IO_L27P_2)

Not connected (* = marked no-connect by the designer): NOR1 3(DU/NC1)* 4(DU/NC2)* 5(DU/NC3)* 6(DU/NC4)* 11(DU/NC5)* 12(DU/NC6)* 13(DU/NC7)* 14(DU/NC8)*; U46 G6(IP_L04N_3/VREF_3) G7(IP_L04P_3) H7(IP_3) J7(IP_L11N_3/VREF_3) M6(IP_L31P_3) M8(IP_L27P_3) N6(IP_L35N_3) N7(IP_L31N_3) N9(IP_2/VREF_2_1)* N12(IP_2/VREF_2_2) P5(IP_L35P_3) P6(IP_L39P_3) P7(IP_L39N_3/VREF_3) P8(IP_2/VREF_2_3) P9(IP_2_1)* P12(IP_2_2) P13(IP_2_3) R8(IP_2_4) R10(IP_2_5)* T11(IP_2_6)* U13(IO_L22P_2/AWAKE) V9(IO_L13N_2) V13(IO_L22N_2/DOUT) V15(IO_L26N_2/D1) W1(IO_L38P_3) W2(IO_L38N_3) Y15(IO_L26P_2/D2) Y18(IO_L30N_2)

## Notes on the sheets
sheet 27
- FPGA, FPGA 2pin conn, SPI Flash, LEDs
- Bank2(3.3V)
- IRQ_FMC1_FPGA_3V3
  connected to I/O pin
  from I only pin
- Bank3(1.8V)
- IRQ_FMC2_FPGA_3V3
  connected to I/O pin
  from I only pin
- Note: Place these TPs nearer
- M2
- M1
- M0
- Details
- 0
- 1
- 1
- Configure from internal flash memory
- 128Mb SPI NOR Flash
- SOC Debug LEDs
- Note:
- COLOR
- LED1
- RED
- LED2
- GREEN
- LED3
- BLUE
- LED4
- BLUE
